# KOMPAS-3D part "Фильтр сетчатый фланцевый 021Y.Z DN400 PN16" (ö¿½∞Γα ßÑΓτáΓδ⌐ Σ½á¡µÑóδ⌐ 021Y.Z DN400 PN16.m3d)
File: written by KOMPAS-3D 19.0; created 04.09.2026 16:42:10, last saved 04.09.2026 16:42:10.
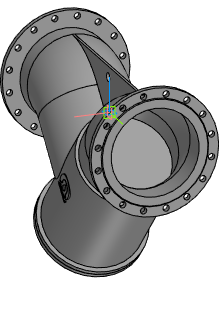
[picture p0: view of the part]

Document properties: Автор: Энергия; Полное имя файла: Z:\3.Личные\sachek\Dendor\_3D для проектировщиков\8.1 Фильтр сетчатый 021Y.Z\021Y.Z_STP\Фильтр сетчатый фланцевый 021Y.Z DN400 PN16.m3d

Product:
- Part/product: Фильтр сетчатый фланцевый 021Y.Z DN400 PN16

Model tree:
1. Операция без истории:1  (labels: Фильтр сетчатый фланцевый 021Y.Z DN400 PN16)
